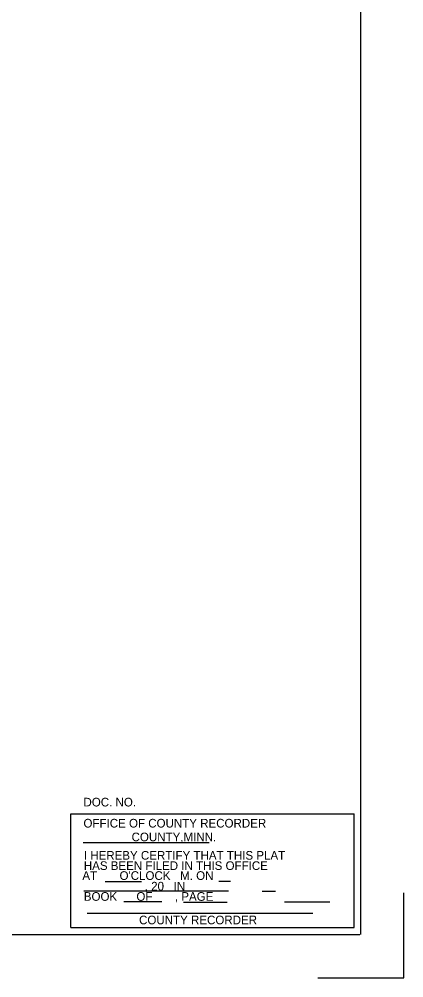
# Model space of a CAD drawing. Extents: x 2147716 to 2176321, y 2125040 to 2131750.
# Drawn here: x 2174558 to 2175003, y 2127114 to 2128223 of the extents above; entities that cross this region are included whole.
import ezdxf

# ---------------------------------------------------------------- set-up
doc = ezdxf.new("R2010")
doc.units = 0
for name, color, linetype in [('PLAT INFO', 7, 'Continuous'), ('PLOT AIDS', 7, 'Continuous'), ('SHT BRDR', 7, 'Continuous')]:
    doc.layers.add(name, color=color, linetype=linetype)

msp = doc.modelspace()

# ---------------------------------------------------------------- linework, layer by layer
at = {"layer": 'PLAT INFO'}
for p, q in [((2174617.4, 2127171.9), (2174617.4, 2127303.5)), ((2174617.4, 2127303.5), (2174945.7, 2127303.5)), ((2174945.7, 2127171.9), (2174945.7, 2127303.5)), ((2174631.8, 2127270.1), (2174777.9, 2127270.1)), ((2174657.4, 2127225), (2174699.5, 2127225)), ((2174802.6, 2127225), (2174788.9, 2127225)), ((2174632.7, 2127214.1), (2174800, 2127214.1)), ((2174839, 2127213.8), (2174854.7, 2127213.8)), ((2174678.8, 2127201.7), (2174722.9, 2127201.7)), ((2174748, 2127201.1), (2174798.5, 2127201.1)), ((2174865.1, 2127201.4), (2174917.7, 2127201.4)), ((2174636.5, 2127188.3), (2174897.7, 2127188.3)), ((2174617.4, 2127171.9), (2174945.7, 2127171.9))]:
    msp.add_line(p, q, dxfattribs=at)
at = {"layer": 'PLOT AIDS'}
for p, q in [((2175003.3, 2127113.5), (2175003.3, 2127211.8)), ((2174903.5, 2127113.5), (2175003.3, 2127113.5))]:
    msp.add_line(p, q, dxfattribs=at)
at = {"layer": 'SHT BRDR'}
for p, q in [((2174953.3, 2127163.5), (2174953.3, 2129272)), ((2171802.3, 2127163.5), (2174952.3, 2127163.5))]:
    msp.add_line(p, q, dxfattribs=at)

# ---------------------------------------------------------------- texts
at = {"layer": 'PLAT INFO'}
for s, p in [('DOC. NO.                ', (2174632.1, 2127311.9)), ('OFFICE OF COUNTY RECORDER ', (2174632.1, 2127287.5)), ('               COUNTY,MINN.', (2174632.1, 2127271.6)), ('I HEREBY CERTIFY THAT THIS PLAT', (2174632.5, 2127250.3)), ('HAS BEEN FILED IN THIS OFFICE', (2174632.5, 2127238.4)), ("AT       O'CLOCK   M. ON", (2174630.8, 2127226.9)), ('                   , 20   IN', (2174632.5, 2127214.6)), ('BOOK      OF       , PAGE     ', (2174632.5, 2127202.7)), ('COUNTY RECORDER', (2174696.5, 2127175.5))]:
    msp.add_text(s, height=10, dxfattribs=at).set_placement(p)

doc.saveas('drawing.dxf')
